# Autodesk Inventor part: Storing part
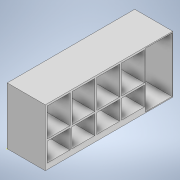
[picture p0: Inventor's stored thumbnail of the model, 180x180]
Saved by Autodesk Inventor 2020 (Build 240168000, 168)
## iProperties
Created: 2020-03
Part Number: Storing part
Material: Generic
Document SubType Name: Modeling
Designer: Darugar
Density: 1 g/cm^3
Appearance: Default
Author: Darugar
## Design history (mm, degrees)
sketch "Sketch1"
  geometry: 1 further point
sketch "Sketch2"
  geometry: 1 further point
sketch "Sketch3"
  geometry: L1 (0, 0)-(300, 0); L2 (300, 0)-(300, -670); L3 (300, -670)-(0, -670); L4 (0, -670)-(0, 0)
  constraints: 8 end point, 2 parallel, 1 horizontal, 1 perpendicular
  dimensions: "d0" = 300 distance of L2.end L3.end; "d1" = 670 distance of L1.end L2.end
extrude "Extrusion1" new body sketch "Sketch3" distance "d2" = 200; taper "d3" = 0 deg
sketch "Sketch4"
  geometry: L1 (0, 212.105)-(10, 212.105); L2 (10, 299.858)-(10, -0.142); L3 (10, 289.858)-(669.856, 289.858); L4 (10, 289.858)-(160, 289.858); L5 (10, 169.858)-(10, 289.858); L6 (10, 289.858)-(130, 289.858); L7 (130, 289.858)-(130, 139.858); L8 (130, 139.858)-(10, 139.858); L9 (10, 139.858)-(10, 289.858); L10 (130.416, 211.352)-(140.416, 211.352); L11 (140.416, 289.858)-(260.416, 289.858); L12 (260.416, 289.858)-(260.416, 139.858); L13 (260.416, 139.858)-(140.416, 139.858); L14 (140.416, 139.858)-(140.416, 289.858); L15 (261.058, 209.189)-(271.058, 209.189); L16 (271.058, 289.858)-(391.058, 289.858); L17 (391.058, 289.858)-(391.058, 139.858); L18 (391.058, 139.858)-(271.058, 139.858); L19 (271.058, 139.858)-(271.058, 289.858); L20 (70, 139.858)-(70, 129.858); L21 (10, 129.858)-(130, 129.858); L22 (130, 129.858)-(130, 29.858); L23 (130, 29.858)-(10, 29.858); L24 (10, 29.858)-(10, 129.858); L25 (130, 79.858)-(140, 79.858); L26 (140, 129.858)-(260, 129.858); L27 (260, 129.858)-(260, 29.858); L28 (260, 29.858)-(140, 29.858); L29 (140, 29.858)-(140, 129.858); L30 (260, 77.794)-(270, 77.794); L31 (270.886, 129.858)-(390.886, 129.858); L32 (390.886, 129.858)-(390.886, 29.858); L33 (390.886, 29.858)-(270.886, 29.858); L34 (270.886, 29.858)-(270.886, 129.858); L35 (391.058, 209.189)-(401.058, 209.189); L36 (401.058, 289.858)-(521.058, 289.858); L37 (521.058, 289.858)-(521.058, 139.858); L38 (521.058, 139.858)-(401.058, 139.858); L39 (401.058, 139.858)-(401.058, 289.858); L40 (401.058, 129.858)-(521.058, 129.858); L41 (521.058, 129.858)-(521.058, 29.858); L42 (521.058, 29.858)-(401.058, 29.858); L43 (401.058, 29.858)-(401.058, 129.858); L44 (521.058, 214.858)-(526.058, 214.858); L45 (670, 300)-(0, 300) reference; L46 (670, 214.858)-(665, 214.858); L47 (594.743, 289.746)-(594.743, 294.746); L48 (526.058, 294.746)-(666.058, 294.746); L49 (666.058, 294.746)-(666.058, 4.746); L50 (666.058, 4.746)-(526.058, 4.746); L51 (526.058, 4.746)-(526.058, 294.746); 9 further points; 1 other entity
  constraints: 100 end point, 18 parallel, 14 horizontal, 11 perpendicular, 8 point on line, 3 midpoint, 3 vertical, 4 other
  dimensions: "d4" = 10 distance of L1.start L1.end; "d10" = 150 distance of L6.end L7.end; "d12" = 10 distance of L10.start L10.end; "d13" = 120 distance of L12.end L13.end; "d14" = 150 distance of L11.end L12.end; "d15" = 10 distance of L15.start L15.end; "d16" = 120 distance of L17.end L18.end; "d19" = 10 distance of L20.start L20.end; "d20" = 120 distance of L22.end L23.end; "d21" = 100 distance of L21.end L22.end; "d23" = 10 distance of L25.start L25.end; "d24" = 120 distance of L27.end L28.end; "d25" = 100 distance of L26.end L27.end; "d27" = 10 distance of L30.start L30.end; "d28" = 120 distance of L32.end L33.end; "d29" = 100 distance of L31.end L32.end; "d30" = 10 distance of L35.start L35.end; "d31" = 120 distance of L37.end L38.end; "d32" = 150 distance of L36.end L37.end; "d33" = 120 distance of L41.end L42.end; "d34" = 100 distance of L40.end L41.end; "d35" = 5 distance of L44.start L44.end; "d38" = 5 distance of L46.start L46.end; "d41" = 5 distance of L47.start L47.end; "d44" = 140 distance of L49.end L50.end; "d45" = 290 distance of L48.end L49.end
sketch "Sketch5"
  geometry: L1 (526.095, 294.719)-(666.095, 294.719); L2 (666.095, 294.719)-(666.095, 289.719); L3 (666.095, 289.719)-(526.095, 289.719); L4 (526.095, 289.719)-(526.095, 294.719); 1 further point
  constraints: 8 end point, 2 parallel, 1 horizontal, 1 perpendicular
  dimensions: "d46" = 140 distance of L2.end L3.end; "d47" = 5 distance of L1.end L2.end
extrude "Extrusion2" cut sketch "Sketch4" distance "d48" = 195; taper "d49" = 0 deg
extrude "Extrusion3" cut sketch "Sketch5" distance "d50" = 195; taper "d51" = 0 deg
sketch "Sketch6"
  geometry: L1 (10, 139.858)-(10, 289.858) reference; L2 (130, 289.858)-(130, 139.858) reference; L3 (10, 289.858)-(130, 139.858); L4 (130, 139.858)-(10, 139.858) reference; L5 (10, 139.858)-(130, 289.858); C1 r 2.5 at (70, 214.858); 1 further point
  constraints: 4 end point, 1 centre point, 1 midpoint
  dimensions: "d52" = 5 diameter of C1
extrude "Extrusion4" cut sketch "Sketch6" distance "d53" = 10; taper "d54" = 0 deg
sketch "Sketch7"
  geometry: L1 (140.416, 139.858)-(140.416, 289.858) reference; L2 (260.416, 139.858)-(140.416, 139.858) reference; L3 (140.416, 289.858)-(260.416, 139.858); L4 (140.416, 289.858)-(260.416, 289.858) reference; L5 (260.416, 289.858)-(140.416, 139.858); L6 (391.058, 139.858)-(271.058, 139.858) reference; L7 (271.058, 289.858)-(391.058, 139.858); L8 (271.058, 139.858)-(271.058, 289.858) reference; L9 (391.058, 289.858)-(271.058, 139.858); L10 (401.058, 139.858)-(401.058, 289.858) reference; L11 (521.058, 139.858)-(401.058, 139.858) reference; L12 (401.058, 289.858)-(521.058, 139.858); L13 (521.058, 289.858)-(401.058, 139.858); C1 r 2.5 at (200.416, 214.858); C2 r 2.5 at (331.058, 214.858); 1 further point
  constraints: 12 end point, 2 centre point, 2 midpoint
  dimensions: "d55" = 5 diameter of C1; "d56" = 5 diameter of C2
extrude "Extrusion5" cut sketch "Sketch7" distance "d57" = 100; taper "d58" = 0 deg
sketch "Sketch8"
  geometry: L1 (401.058, 139.858)-(401.058, 289.858) reference; L2 (521.058, 139.858)-(401.058, 139.858) reference; L3 (401.058, 289.858)-(521.058, 139.858); L4 (521.058, 289.858)-(401.058, 139.858); C1 r 2.5 at (461.058, 214.858); 1 further point
  constraints: 4 end point, 1 centre point, 1 midpoint
  dimensions: "d59" = 5 diameter of C1
extrude "Extrusion6" cut sketch "Sketch8" distance "d60" = 100; taper "d61" = 0 deg
body "Solid1"
